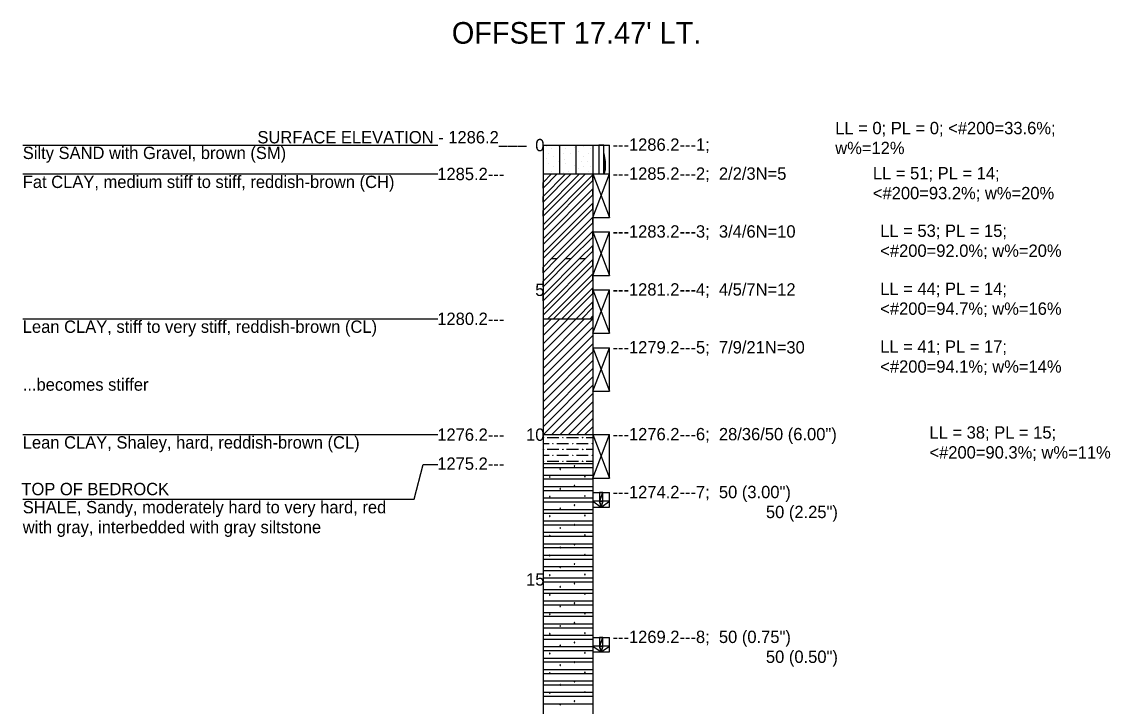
# Model space of a CAD drawing. Extents: x -6 to 173, y 24 to 64.
# Drawn here: x 13.07 to 24, y 43.76 to 50.63 of the extents above; entities that cross this region are included whole.
import ezdxf

# ---------------------------------------------------------------- set-up
doc = ezdxf.new("R2010")
doc.units = 0

# ---------------------------------------------------------------- blocks, each defined once
blk = doc.blocks.new('POINT_DISPLAY')
blk.add_line((0, 0), (0, 0))

msp = doc.modelspace()

# ---------------------------------------------------------------- linework, layer by layer
for points in [[(13.081, 49.392), (17.248, 49.392)], [(18.306, 49.392), (18.306, 37.183)], [(18.306, 49.392), (18.806, 49.392)], [(18.472, 49.102), (18.472, 49.392)], [(18.639, 49.102), (18.639, 49.392)], [(18.806, 49.392), (18.972, 49.392)], [(18.806, 49.392), (18.806, 37.183)], [(18.972, 49.102), (18.972, 49.392)], [(13.081, 49.102), (17.248, 49.102)], [(18.306, 49.102), (18.806, 49.102)], [(18.806, 49.102), (18.972, 49.102)], [(18.806, 49.102), (18.972, 48.665)], [(18.806, 48.665), (18.972, 49.102)], [(18.806, 49.102), (18.972, 49.102)], [(18.972, 48.665), (18.972, 49.102)], [(18.806, 48.665), (18.972, 48.665)], [(18.806, 48.52), (18.972, 48.084)], [(18.806, 48.084), (18.972, 48.52)], [(18.806, 48.52), (18.972, 48.52)], [(18.972, 48.084), (18.972, 48.52)], [(18.806, 48.084), (18.972, 48.084)], [(18.806, 47.939), (18.972, 47.503)], [(18.806, 47.503), (18.972, 47.939)], [(18.806, 47.939), (18.972, 47.939)], [(18.972, 47.503), (18.972, 47.939)], [(13.081, 47.648), (17.248, 47.648)], [(18.306, 47.648), (18.806, 47.648)], [(18.306, 47.565), (18.389, 47.648)], [(18.306, 47.481), (18.472, 47.648)], [(18.306, 47.398), (18.556, 47.648)], [(18.306, 47.315), (18.639, 47.648)], [(18.306, 47.231), (18.722, 47.648)], [(18.306, 47.148), (18.806, 47.648)], [(18.306, 47.065), (18.806, 47.565)], [(18.306, 46.981), (18.806, 47.481)], [(18.806, 47.503), (18.972, 47.503)], [(18.306, 46.898), (18.806, 47.398)], [(18.806, 47.357), (18.972, 46.921)], [(18.806, 46.921), (18.972, 47.357)], [(18.806, 47.357), (18.972, 47.357)], [(18.972, 46.921), (18.972, 47.357)], [(18.306, 46.815), (18.806, 47.315)], [(18.306, 46.731), (18.806, 47.231)], [(18.306, 46.648), (18.806, 47.148)], [(18.306, 46.565), (18.806, 47.065)], [(18.31, 46.485), (18.806, 46.981)], [(18.393, 46.485), (18.806, 46.898)], [(18.806, 46.921), (18.972, 46.921)], [(18.476, 46.485), (18.806, 46.815)], [(18.56, 46.485), (18.806, 46.731)], [(18.643, 46.485), (18.806, 46.648)], [(18.726, 46.485), (18.806, 46.565)], [(13.081, 46.485), (17.248, 46.485)], [(18.306, 46.485), (18.806, 46.485)], [(18.306, 46.456), (18.31, 46.456), (18.31, 46.452), (18.306, 46.456)], [(18.345, 46.456), (18.463, 46.456)], [(18.503, 46.456), (18.506, 46.456), (18.503, 46.452), (18.503, 46.456)], [(18.542, 46.456), (18.66, 46.456)], [(18.699, 46.456), (18.703, 46.456), (18.703, 46.452), (18.699, 46.456)], [(18.739, 46.456), (18.806, 46.456)], [(18.806, 46.485), (18.972, 46.049)], [(18.806, 46.049), (18.972, 46.485)], [(18.806, 46.485), (18.972, 46.485)], [(18.972, 46.049), (18.972, 46.485)], [(18.306, 46.397), (18.365, 46.397)], [(18.404, 46.397), (18.408, 46.397), (18.404, 46.393), (18.404, 46.397)], [(18.443, 46.397), (18.562, 46.397)], [(18.601, 46.397), (18.605, 46.397), (18.605, 46.393), (18.601, 46.397)], [(18.64, 46.397), (18.699, 46.397)], [(18.699, 46.397), (18.758, 46.397)], [(18.798, 46.397), (18.802, 46.397), (18.798, 46.393), (18.798, 46.397)], [(18.306, 46.338), (18.31, 46.338), (18.31, 46.334), (18.306, 46.338)], [(18.306, 46.279), (18.365, 46.279)], [(18.345, 46.338), (18.463, 46.338)], [(18.404, 46.279), (18.408, 46.279), (18.404, 46.275), (18.404, 46.279)], [(18.443, 46.279), (18.562, 46.279)], [(18.503, 46.338), (18.506, 46.338), (18.503, 46.334), (18.503, 46.338)], [(18.542, 46.338), (18.66, 46.338)], [(18.601, 46.279), (18.605, 46.279), (18.605, 46.275), (18.601, 46.279)], [(18.64, 46.279), (18.699, 46.279)], [(18.699, 46.338), (18.703, 46.338), (18.703, 46.334), (18.699, 46.338)], [(18.699, 46.279), (18.758, 46.279)], [(18.739, 46.338), (18.806, 46.338)], [(18.798, 46.279), (18.802, 46.279), (18.798, 46.275), (18.798, 46.279)], [(13.081, 45.836), (17.012, 45.836), (17.1, 46.185), (17.248, 46.185)], [(18.306, 46.219), (18.31, 46.219), (18.31, 46.216), (18.306, 46.219)], [(18.306, 46.194), (18.806, 46.194)], [(18.306, 46.194), (18.806, 46.194)], [(18.306, 46.155), (18.806, 46.155)], [(18.345, 46.219), (18.463, 46.219)], [(18.481, 46.138), (18.479, 46.141), (18.476, 46.141), (18.474, 46.138), (18.476, 46.136), (18.479, 46.136), (18.481, 46.138)], [(18.503, 46.219), (18.506, 46.219), (18.503, 46.216), (18.503, 46.219)], [(18.542, 46.219), (18.66, 46.219)], [(18.623, 46.17), (18.622, 46.173), (18.618, 46.173), (18.617, 46.17), (18.618, 46.167), (18.622, 46.167), (18.623, 46.17)], [(18.699, 46.219), (18.703, 46.219), (18.703, 46.216), (18.699, 46.219)], [(18.739, 46.219), (18.806, 46.219)], [(18.306, 46.079), (18.806, 46.079)], [(18.306, 46.04), (18.806, 46.04)], [(18.376, 46.059), (18.374, 46.062), (18.371, 46.062), (18.37, 46.059), (18.371, 46.057), (18.374, 46.057), (18.376, 46.059)], [(18.729, 46.066), (18.727, 46.069), (18.724, 46.069), (18.722, 46.066), (18.724, 46.063), (18.727, 46.063), (18.729, 46.066)], [(18.806, 46.049), (18.972, 46.049)], [(18.306, 45.965), (18.806, 45.965)], [(18.306, 45.925), (18.806, 45.925)], [(18.481, 45.942), (18.479, 45.944), (18.476, 45.944), (18.474, 45.942), (18.476, 45.939), (18.479, 45.939), (18.481, 45.942)], [(18.623, 45.973), (18.622, 45.976), (18.618, 45.976), (18.617, 45.973), (18.618, 45.971), (18.622, 45.971), (18.623, 45.973)], [(18.806, 45.904), (18.972, 45.904)], [(18.972, 45.758), (18.972, 45.904)], [(18.306, 45.85), (18.806, 45.85)], [(18.306, 45.81), (18.806, 45.81)], [(18.376, 45.863), (18.374, 45.865), (18.371, 45.865), (18.37, 45.863), (18.371, 45.86), (18.374, 45.86), (18.376, 45.863)], [(18.729, 45.869), (18.727, 45.872), (18.724, 45.872), (18.722, 45.869), (18.724, 45.866), (18.727, 45.866), (18.729, 45.869)], [(18.306, 45.735), (18.806, 45.735)], [(18.306, 45.696), (18.806, 45.696)], [(18.481, 45.745), (18.479, 45.748), (18.476, 45.748), (18.474, 45.745), (18.476, 45.742), (18.479, 45.742), (18.481, 45.745)], [(18.623, 45.777), (18.622, 45.779), (18.618, 45.779), (18.617, 45.777), (18.618, 45.774), (18.622, 45.774), (18.623, 45.777)], [(18.806, 45.758), (18.972, 45.758)], [(18.306, 45.62), (18.806, 45.62)], [(18.306, 45.581), (18.806, 45.581)], [(18.376, 45.666), (18.374, 45.669), (18.371, 45.669), (18.37, 45.666), (18.371, 45.663), (18.374, 45.663), (18.376, 45.666)], [(18.623, 45.58), (18.622, 45.583), (18.618, 45.583), (18.617, 45.58), (18.618, 45.577), (18.622, 45.577), (18.623, 45.58)], [(18.729, 45.672), (18.727, 45.675), (18.724, 45.675), (18.722, 45.672), (18.724, 45.669), (18.727, 45.669), (18.729, 45.672)], [(18.306, 45.505), (18.806, 45.505)], [(18.376, 45.469), (18.374, 45.472), (18.371, 45.472), (18.37, 45.469), (18.371, 45.466), (18.374, 45.466), (18.376, 45.469)], [(18.481, 45.548), (18.479, 45.551), (18.476, 45.551), (18.474, 45.548), (18.476, 45.545), (18.479, 45.545), (18.481, 45.548)], [(18.729, 45.475), (18.727, 45.478), (18.724, 45.478), (18.722, 45.475), (18.724, 45.473), (18.727, 45.473), (18.729, 45.475)], [(18.306, 45.466), (18.806, 45.466)], [(18.306, 45.39), (18.806, 45.39)], [(18.623, 45.383), (18.622, 45.386), (18.618, 45.386), (18.617, 45.383), (18.618, 45.38), (18.622, 45.38), (18.623, 45.383)], [(18.306, 45.351), (18.806, 45.351)], [(18.306, 45.276), (18.806, 45.276)], [(18.376, 45.272), (18.374, 45.275), (18.371, 45.275), (18.37, 45.272), (18.371, 45.269), (18.374, 45.269), (18.376, 45.272)], [(18.481, 45.351), (18.479, 45.354), (18.476, 45.354), (18.474, 45.351), (18.476, 45.348), (18.479, 45.348), (18.481, 45.351)], [(18.729, 45.279), (18.727, 45.281), (18.724, 45.281), (18.722, 45.279), (18.724, 45.276), (18.727, 45.276), (18.729, 45.279)], [(18.306, 45.236), (18.806, 45.236)], [(18.306, 45.161), (18.806, 45.161)], [(18.481, 45.154), (18.479, 45.157), (18.476, 45.157), (18.474, 45.154), (18.476, 45.151), (18.479, 45.151), (18.481, 45.154)], [(18.623, 45.186), (18.622, 45.189), (18.618, 45.189), (18.617, 45.186), (18.618, 45.183), (18.622, 45.183), (18.623, 45.186)], [(18.306, 45.121), (18.806, 45.121)], [(18.306, 45.046), (18.806, 45.046)], [(18.376, 45.075), (18.374, 45.078), (18.371, 45.078), (18.37, 45.075), (18.371, 45.072), (18.374, 45.072), (18.376, 45.075)], [(18.729, 45.082), (18.727, 45.085), (18.724, 45.085), (18.722, 45.082), (18.724, 45.079), (18.727, 45.079), (18.729, 45.082)], [(18.306, 45.007), (18.806, 45.007)], [(18.306, 44.931), (18.806, 44.931)], [(18.481, 44.957), (18.479, 44.96), (18.476, 44.96), (18.474, 44.957), (18.476, 44.954), (18.479, 44.954), (18.481, 44.957)], [(18.623, 44.989), (18.622, 44.992), (18.618, 44.992), (18.617, 44.989), (18.618, 44.986), (18.622, 44.986), (18.623, 44.989)], [(18.306, 44.892), (18.806, 44.892)], [(18.306, 44.816), (18.806, 44.816)], [(18.376, 44.878), (18.374, 44.881), (18.371, 44.881), (18.37, 44.878), (18.371, 44.875), (18.374, 44.875), (18.376, 44.878)], [(18.729, 44.885), (18.727, 44.888), (18.724, 44.888), (18.722, 44.885), (18.724, 44.882), (18.727, 44.882), (18.729, 44.885)], [(18.306, 44.777), (18.806, 44.777)], [(18.306, 44.701), (18.806, 44.701)], [(18.481, 44.76), (18.479, 44.763), (18.476, 44.763), (18.474, 44.761), (18.476, 44.758), (18.479, 44.758), (18.481, 44.76)], [(18.623, 44.792), (18.622, 44.795), (18.618, 44.795), (18.617, 44.792), (18.618, 44.79), (18.622, 44.79), (18.623, 44.792)], [(18.306, 44.662), (18.806, 44.662)], [(18.376, 44.682), (18.374, 44.684), (18.371, 44.684), (18.37, 44.682), (18.371, 44.679), (18.374, 44.679), (18.376, 44.682)], [(18.623, 44.595), (18.622, 44.598), (18.618, 44.598), (18.617, 44.595), (18.618, 44.593), (18.622, 44.593), (18.623, 44.595)], [(18.729, 44.688), (18.727, 44.691), (18.724, 44.691), (18.722, 44.688), (18.724, 44.685), (18.727, 44.685), (18.729, 44.688)], [(18.306, 44.587), (18.806, 44.587)], [(18.306, 44.547), (18.806, 44.547)], [(18.376, 44.485), (18.374, 44.487), (18.371, 44.487), (18.37, 44.485), (18.371, 44.482), (18.374, 44.482), (18.376, 44.485)], [(18.481, 44.564), (18.479, 44.566), (18.476, 44.566), (18.474, 44.564), (18.476, 44.561), (18.479, 44.561), (18.481, 44.564)], [(18.729, 44.491), (18.727, 44.494), (18.724, 44.494), (18.722, 44.491), (18.724, 44.488), (18.727, 44.488), (18.729, 44.491)], [(18.306, 44.472), (18.806, 44.472)], [(18.306, 44.432), (18.806, 44.432)], [(18.623, 44.399), (18.622, 44.401), (18.618, 44.401), (18.617, 44.399), (18.618, 44.396), (18.622, 44.396), (18.623, 44.399)], [(18.806, 44.45), (18.972, 44.45)], [(18.972, 44.305), (18.972, 44.45)], [(18.306, 44.357), (18.806, 44.357)], [(18.306, 44.318), (18.806, 44.318)], [(18.376, 44.288), (18.374, 44.291), (18.371, 44.291), (18.37, 44.288), (18.371, 44.285), (18.374, 44.285), (18.376, 44.288)], [(18.481, 44.367), (18.479, 44.37), (18.476, 44.37), (18.474, 44.367), (18.476, 44.364), (18.479, 44.364), (18.481, 44.367)], [(18.729, 44.294), (18.727, 44.297), (18.724, 44.297), (18.722, 44.294), (18.724, 44.291), (18.727, 44.291), (18.729, 44.294)], [(18.806, 44.305), (18.972, 44.305)], [(18.306, 44.242), (18.806, 44.242)], [(18.306, 44.203), (18.806, 44.203)], [(18.481, 44.17), (18.479, 44.173), (18.476, 44.173), (18.474, 44.17), (18.476, 44.167), (18.479, 44.167), (18.481, 44.17)], [(18.623, 44.202), (18.622, 44.205), (18.618, 44.205), (18.617, 44.202), (18.618, 44.199), (18.622, 44.199), (18.623, 44.202)], [(18.306, 44.127), (18.806, 44.127)], [(18.306, 44.088), (18.806, 44.088)], [(18.376, 44.091), (18.374, 44.094), (18.371, 44.094), (18.37, 44.091), (18.371, 44.088), (18.374, 44.088), (18.376, 44.091)], [(18.729, 44.097), (18.727, 44.1), (18.724, 44.1), (18.722, 44.097), (18.724, 44.095), (18.727, 44.095), (18.729, 44.097)], [(18.306, 44.012), (18.806, 44.012)], [(18.306, 43.973), (18.806, 43.973)], [(18.481, 43.973), (18.479, 43.976), (18.476, 43.976), (18.474, 43.973), (18.476, 43.97), (18.479, 43.97), (18.481, 43.973)], [(18.623, 44.005), (18.622, 44.008), (18.618, 44.008), (18.617, 44.005), (18.618, 44.002), (18.622, 44.002), (18.623, 44.005)], [(18.306, 43.898), (18.806, 43.898)], [(18.306, 43.858), (18.806, 43.858)], [(18.376, 43.894), (18.374, 43.897), (18.371, 43.897), (18.37, 43.894), (18.371, 43.891), (18.374, 43.891), (18.376, 43.894)], [(18.729, 43.901), (18.727, 43.903), (18.724, 43.903), (18.722, 43.901), (18.724, 43.898), (18.727, 43.898), (18.729, 43.901)], [(18.306, 43.783), (18.806, 43.783)], [(18.481, 43.776), (18.479, 43.779), (18.476, 43.779), (18.474, 43.776), (18.476, 43.773), (18.479, 43.773), (18.481, 43.776)], [(18.623, 43.808), (18.622, 43.811), (18.618, 43.811), (18.617, 43.808), (18.618, 43.805), (18.622, 43.805), (18.623, 43.808)]]:
    msp.add_lwpolyline(points)
for points in [[(18.864, 49.392), (18.864, 49.102), (18.914, 49.102), (18.914, 49.392)], [(18.929, 49.226), (18.923, 49.267), (18.914, 49.307), (18.929, 49.226)], [(18.914, 49.307), (18.914, 49.102), (18.929, 49.226), (18.914, 49.307)], [(18.914, 49.102), (18.929, 49.142), (18.929, 49.226), (18.914, 49.102)], [(18.929, 49.142), (18.931, 49.184), (18.929, 49.226), (18.929, 49.142)], [(18.306, 48.735), (18.672, 49.102), (18.731, 49.102), (18.306, 48.677)], [(18.306, 48.877), (18.531, 49.102), (18.589, 49.102), (18.306, 48.818)], [(18.306, 49.018), (18.389, 49.102), (18.447, 49.102), (18.306, 48.96)], [(18.806, 49.035), (18.806, 49.093), (18.306, 48.593), (18.306, 48.535)], [(18.914, 49.102), (18.923, 49.102), (18.929, 49.142), (18.914, 49.102)], [(18.806, 48.893), (18.806, 48.952), (18.306, 48.452), (18.306, 48.393)], [(18.806, 48.752), (18.806, 48.81), (18.306, 48.31), (18.306, 48.252)], [(18.447, 48.252), (18.806, 48.61), (18.806, 48.668), (18.389, 48.252)], [(18.589, 48.252), (18.806, 48.468), (18.806, 48.527), (18.531, 48.252)], [(18.731, 48.252), (18.806, 48.327), (18.806, 48.385), (18.672, 48.252)], [(18.306, 47.885), (18.672, 48.252), (18.731, 48.252), (18.306, 47.827)], [(18.306, 48.027), (18.531, 48.252), (18.589, 48.252), (18.306, 47.968)], [(18.306, 48.168), (18.389, 48.252), (18.447, 48.252), (18.306, 48.11)], [(18.806, 48.185), (18.806, 48.243), (18.306, 47.743), (18.306, 47.685)], [(18.806, 48.043), (18.806, 48.101), (18.352, 47.648), (18.411, 47.648)], [(18.806, 47.901), (18.806, 47.96), (18.494, 47.648), (18.552, 47.648)], [(18.806, 47.76), (18.806, 47.818), (18.636, 47.648), (18.694, 47.648)], [(18.777, 47.648), (18.806, 47.648), (18.806, 47.677), (18.777, 47.648)], [(18.872, 45.817), (18.906, 45.817), (18.906, 45.904), (18.872, 45.817)], [(18.872, 45.817), (18.906, 45.904), (18.872, 45.904), (18.872, 45.817)], [(18.872, 45.817), (18.806, 45.817), (18.889, 45.758), (18.872, 45.817)], [(18.872, 45.817), (18.889, 45.758), (18.906, 45.817), (18.872, 45.817)], [(18.889, 45.758), (18.972, 45.817), (18.906, 45.817), (18.889, 45.758)], [(18.872, 44.363), (18.906, 44.363), (18.906, 44.45), (18.872, 44.363)], [(18.872, 44.363), (18.906, 44.45), (18.872, 44.45), (18.872, 44.363)], [(18.872, 44.363), (18.806, 44.363), (18.889, 44.305), (18.872, 44.363)], [(18.872, 44.363), (18.889, 44.305), (18.906, 44.363), (18.872, 44.363)], [(18.889, 44.305), (18.972, 44.363), (18.906, 44.363), (18.889, 44.305)]]:
    msp.add_lwpolyline(points, close=True)

# ---------------------------------------------------------------- block references
at = {"xscale": 0.01, "yscale": 0.01}
for p in [(18.31, 49.33), (18.335, 49.38), (18.36, 49.305), (18.385, 49.355), (18.46, 49.38), (18.477, 49.332), (18.51, 49.305), (18.535, 49.355), (18.585, 49.305), (18.625, 49.367), (18.66, 49.33), (18.71, 49.38), (18.76, 49.305), (18.785, 49.355), (18.335, 49.255), (18.36, 49.205), (18.41, 49.28), (18.46, 49.23), (18.523, 49.248), (18.535, 49.205), (18.624, 49.191), (18.635, 49.255), (18.692, 49.226), (18.71, 49.28), (18.752, 49.223), (18.801, 49.23), (18.31, 49.155), (18.385, 49.13), (18.41, 49.18), (18.435, 49.105), (18.474, 49.172), (18.512, 49.119), (18.56, 49.13), (18.61, 49.105), (18.66, 49.155), (18.71, 49.18), (18.76, 49.13), (18.785, 49.18)]:
    msp.add_blockref('POINT_DISPLAY', p, dxfattribs=at)

# ---------------------------------------------------------------- texts
for s, height, p in [("OFFSET 17.47' LT.", 0.217, (17.389, 50.41)), ('LL = 0; PL = 0; <#200=33.6%;', 0.124, (21.239, 49.501)), ('SURFACE ELEVATION - 1286.2___', 0.124, (15.437, 49.409)), ('0', 0.124, (18.227, 49.33)), ('---1286.2---1;', 0.124, (19.002, 49.335)), ('w%=12%', 0.124, (21.239, 49.301)), ('Silty SAND with Gravel, brown (SM)', 0.124, (13.081, 49.252)), ('Fat CLAY, medium stiff to stiff, reddish-brown (CH)', 0.124, (13.081, 48.961)), ('1285.2---', 0.124, (17.243, 49.04)), ('---1285.2---2;  2/2/3N=5', 0.124, (19.002, 49.044)), ('LL = 51; PL = 14;', 0.124, (21.617, 49.048)), ('<#200=93.2%; w%=20%', 0.124, (21.617, 48.848)), ('---1283.2---3;  3/4/6N=10', 0.124, (19.002, 48.463)), ('LL = 53; PL = 15;', 0.124, (21.691, 48.47)), ('<#200=92.0%; w%=20%', 0.124, (21.691, 48.27)), ('5', 0.124, (18.227, 47.877)), ('---1281.2---4;  4/5/7N=12', 0.124, (19.002, 47.881)), ('LL = 44; PL = 14;', 0.124, (21.691, 47.888)), ('<#200=94.7%; w%=16%', 0.124, (21.691, 47.688)), ('1280.2---', 0.124, (17.243, 47.586)), ('Lean CLAY, stiff to very stiff, reddish-brown (CL)', 0.124, (13.081, 47.507)), ('---1279.2---5;  7/9/21N=30', 0.124, (19.002, 47.3)), ('LL = 41; PL = 17;', 0.124, (21.691, 47.307)), ('<#200=94.1%; w%=14%', 0.124, (21.691, 47.107)), ('...becomes stiffer', 0.124, (13.081, 46.926)), ('LL = 38; PL = 15;', 0.124, (22.185, 46.445)), ('Lean CLAY, Shaley, hard, reddish-brown (CL)', 0.124, (13.081, 46.345)), ('1276.2---', 0.124, (17.243, 46.423)), ('10', 0.124, (18.135, 46.423)), ('---1276.2---6;  28/36/50 (6.00")', 0.124, (19.002, 46.428)), ('<#200=90.3%; w%=11%', 0.124, (22.185, 46.245)), ('1275.2---', 0.124, (17.243, 46.132)), ('TOP OF BEDROCK', 0.124, (13.067, 45.877)), ('---1274.2---7;  50 (3.00")', 0.124, (19.002, 45.847)), ('SHALE, Sandy, moderately hard to very hard, red', 0.124, (13.081, 45.695)), ('50 (2.25")', 0.124, (20.543, 45.647)), ('with gray, interbedded with gray siltstone', 0.124, (13.081, 45.495)), ('15', 0.124, (18.135, 44.97)), ('---1269.2---8;  50 (0.75")', 0.124, (19.002, 44.393)), ('50 (0.50")', 0.124, (20.543, 44.193))]:
    msp.add_text(s, height=height).set_placement(p)

doc.saveas('drawing.dxf')
